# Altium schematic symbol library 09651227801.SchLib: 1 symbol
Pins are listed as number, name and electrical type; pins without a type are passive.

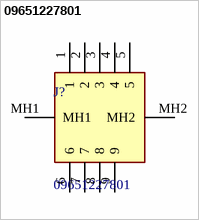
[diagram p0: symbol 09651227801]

## 09651227801
designator J?
D-Sub 9pin male angled 2.54mm pitch, stamped, w/o board locks, M3, PL3; Manufacturer_Name: HARTING; Geometry.Height: 13.6mm
footprint 09651227801
pins: 1, 2, 3, 4, 5, 6, 7, 8, 9, MH1, MH2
